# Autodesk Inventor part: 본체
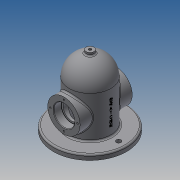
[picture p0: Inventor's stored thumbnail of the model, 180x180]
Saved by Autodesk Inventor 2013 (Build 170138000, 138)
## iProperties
Created: 2019-11
Part Number: 본체
Material: 일반
Document SubType Name: Modeling
Designer: Administrator
Density: 1 g/cm^3
Author: Administrator
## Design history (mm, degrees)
sketch "스케치1"
  geometry: C1 r 40 at (0, 0); 1 further point
  constraints: 1 centre point, 1 coincident
  dimensions: "d0" = 80 diameter of C1
extrude "돌출1" new body sketch "스케치1" distance "d1" = 90; taper "d2" = 0 deg
sketch "스케치2"
  geometry: L1 (-40, 0)-(40, 0); A1 r 40 centre (0, 0) between (-40, 0) and (40, 0) reference; A2 r 40 centre (0, 0) between (40, 0) and (-40, 0); 1 further point
  constraints: 4 point on circle, 2 coincident, 2 end point, 1 centre point, 1 midpoint
  dimensions: "d3" = 80 distance of L1.start L1.end
revolve "회전1" sketch "스케치2" stored, may be unused: angle "d5" = 90 deg
feature "쉘1" dims "d6" = 10
sketch "스케치3"
  geometry: C1 r 40 at (0, 0) reference; C2 r 70 at (0, 0)
  constraints: 1 centre point, 1 coincident
  dimensions: "d7" = 140 diameter of C2
extrude "돌출2" join sketch "스케치3" distance "d8" = 10; taper "d9" = 0 deg
node "작업 평면1"
sketch "스케치4"
  geometry: L1 (70, 0)-(-70, 0) reference; C1 r 31 at (0, 50); 1 further point
  constraints: 1 centre point, 1 vertical alignment
  dimensions: "d11" = 62 diameter of C1; "d12" = 50 distance from line of L1 C1.centre
extrude "돌출3" join sketch "스케치4" stored distance "d13" = 10; taper "d14" = 0 deg
sketch "스케치5"
  geometry: C1 r 31 at (0, 0) reference; C2 r 16.5 at (0, 0); 1 further point
  constraints: 1 centre point, 1 coincident
  dimensions: "d15" = 33 diameter of C2
extrude "돌출4" cut sketch "스케치5" stored distance "d16" = 10; taper "d17" = 0 deg
sketch "스케치6"
  geometry: C1 r 16.5 at (0, 0) reference; C2 r 31 at (0, 0) reference; C3 r 20 at (0, 0); 1 further point
  constraints: 1 centre point, 1 coincident
  dimensions: "d18" = 40 diameter of C3
extrude "돌출5" cut sketch "스케치6" distance "d19" = 15; taper "d20" = 0 deg
node "작업 평면2"
sketch "스케치7"
  geometry: C1 r 7.5 at (0, 0); 1 further point
  constraints: 1 centre point, 1 coincident
  dimensions: "d22" = 15 diameter of C1
extrude "돌출6" join sketch "스케치7" stored distance "d23" = 15; taper "d24" = 0 deg
sketch "스케치8"
  geometry: 1 further point
hole "구멍1" sketch "스케치8" at (0, 0) diameter "d25" = 5.188; stored, may be unused: countersink angle "d29" = 90 deg, drill point angle "d31" = 118 deg; dims "d26" = 6, "d27" = 4, "d28" = 2, "d30" = 57
sketch "스케치9" dims "d32" = 52
  geometry: C1 r 31 at (0, 0) reference; 3 further points
  constraints: 2 vertical alignment, 1 coincident, 2 other
hole "구멍2" sketch "스케치9" at (0, 26) diameter "d33" = 3.242; stored, may be unused: countersink angle "d37" = 90 deg, drill point angle "d39" = 118 deg; dims "d34" = 8, "d35" = 4, "d36" = 2, "d38" = 10
sketch "스케치10" dims "d43" = 110
  geometry: C1 r 40 at (0, 0) reference; C2 r 70 at (0, 0) reference; C3 r 4.5 at (0, -55); 1 further point
  constraints: 2 vertical alignment, 1 centre point, 3 other
  dimensions: "d44" = 9 diameter of C3
extrude "돌출7" cut sketch "스케치10" stored distance "d45" = 15; taper "d46" = 0 deg
node "작업 평면4"
  node "작업 평면3"
sketch "스케치11"
  geometry: L1 (70, 0)-(-70, 0) reference; 3 further points
  constraints: 1 midpoint, 1 vertical alignment, 1 other
  dimensions: "d48" = 50 distance from line of L1 point (0, 50)
feature "엠보싱1" sketch "스케치11" dims "d49" = 0.5, "d50" = 0
fillet "모깎기1" dims "d51" = 0.3
chamfer "모따기1" distance "d52" = 1; stored, may be unused: second distance "d53" = 2, angle "d54" = 45 deg
fillet "모깎기2" dims "d55" = 3
node "솔리드1"
mirror "대칭1"
pattern_circular "원형 패턴1" dims angle "d41" = 360 deg
mirror "대칭2"
mirror "대칭3"
node "절단 모서리 투영1"
other parameters: "d21" = -135, "d47" = 21
